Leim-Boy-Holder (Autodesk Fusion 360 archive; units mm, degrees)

design "Leim-Boy-Holder" references "Base"
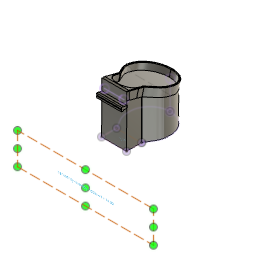
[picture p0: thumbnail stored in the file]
parameter "padding" = 5
parameter "wall_thickness" = 3
parameter "height" = 14
parameter "bottle_bottom_height" = 24
component_insert "Component Insert"
sketch "Reference" plane through (0, 55.6118, 0) normal (0, 1, 0) x axis (-1, 0, 0)
  line L1 (0, 52.4859) -> (0, 47.1259)
  line L2 (-40, 52.4859) -> (0, 52.4859)
  line L3 (-40, 47.1259) -> (-40, 52.4859)
  line L4 (0, 47.1259) -> (-40, 47.1259)
  line L5 (-40, 60) -> (0, 60)
canvas "Canvas2"
sketch "Leim Boy Base" plane through (0, 0, 0) normal (0, 0, 1) x axis (1, 0, 0)
  line L1 (-18.3701, 3.7479) -> (86.6381, 2.2286)
  curve K1 (-18.3701, 3.7479) -> (86.6381, 2.2286)
  curve K2 (86.889, 9.7087) -> (86.3872, -5.2516)
  curve K3 (83.9228, 20.464) -> (88.3484, -2.1492)
  curve K4 (57.7933, 21.4643) -> (85.6809, 20.0093)
  curve K5 (27.9092, 40.0205) -> (51.6261, 26.3959)
  curve K6 (54.8294, 23.88) -> (63.7814, 18.7373)
  curve K7 (26.0434, 38.2552) -> (33.2573, 36.115)
  curve K8 (2.0377, 36.5037) -> (24.2104, 38.799)
  curve K9 (-18.716, -11.6628) -> (-18.0242, 19.1587)
  line L2 (-18.3701, 3.7479) -> (86.6381, 2.2286)
  curve K10 (-18.3701, 3.7479) -> (86.6381, 2.2286)
  curve K11 (86.6725, -5.2557) -> (86.6037, 9.7128)
  curve K12 (83.3963, -15.9207) -> (88.4744, 6.5551)
  curve K13 (57.2488, -16.1646) -> (85.1669, -15.517)
  curve K14 (54.2163, -18.4935) -> (63.3134, -13.612)
  curve K15 (26.8403, -33.8484) -> (50.9415, -20.9157)
  curve K16 (25.0265, -32.0299) -> (32.2993, -30.0992)
  curve K17 (1.0814, -29.5846) -> (23.1785, -32.5204)
  curve K18 (-18.27, 19.1623) -> (-18.4703, -11.6664)
  curve K19 (61.6573, 25.7332) -> (91.6382, 2.1562)
  curve K20 (-23.3698, 3.8203) -> (61.6573, 25.7332)
  curve K21 (-23.3698, 3.8203) -> (60.9877, -20.5435)
  curve K22 (60.9877, -20.5435) -> (91.6382, 2.1562)
  curve K23 (62.6874, 28.6657) -> (94.6382, 2.1128)
  curve K24 (-26.3696, 3.8637) -> (62.6874, 28.6657)
  curve K25 (-26.3696, 3.8637) -> (61.9325, -23.5045)
  curve K26 (61.9325, -23.5045) -> (94.6382, 2.1128)
  point P2 (86.6381, 2.2286)
  point P4 (86.1356, 9.1574)
  point P5 (71.7371, 20.7368)
  point P7 (39.7676, 33.2082)
  point P6 (59.3054, 21.3087)
  point P8 (29.6504, 37.1851)
  point P9 (13.124, 37.6514)
  point P3 (-18.3701, 3.7479)
  point P22 (24.2104, 38.799)
  point P26 (86.6381, 2.2286)
  point P27 (-18.3701, 3.7479)
  point P28 (85.9354, -4.6828)
  point P29 (71.2079, -15.8408)
  point P30 (58.7648, -16.0527)
  point P31 (38.8909, -27.382)
  point P32 (28.6629, -31.0645)
  point P33 (12.1299, -31.0525)
  point P10 (86.3872, -5.2516)
  point P34 (86.6037, 9.7128)
  point P11 (86.889, 9.7087)
  point P35 (86.6725, -5.2557)
  point P12 (88.3484, -2.1492)
  point P36 (88.4744, 6.5551)
  point P13 (83.9228, 20.464)
  point P37 (83.3963, -15.9207)
  point P14 (85.6809, 20.0093)
  point P38 (85.1669, -15.517)
  point P15 (57.7933, 21.4643)
  point P39 (57.2488, -16.1646)
  point P16 (51.6261, 26.3959)
  point P42 (50.9415, -20.9157)
  point P17 (27.9092, 40.0205)
  point P43 (26.8403, -33.8484)
  point P18 (63.7814, 18.7373)
  point P40 (63.3134, -13.612)
  point P19 (54.8294, 23.88)
  point P41 (54.2163, -18.4935)
  point P20 (33.2573, 36.115)
  point P44 (32.2993, -30.0992)
  point P21 (26.0434, 38.2552)
  point P45 (25.0265, -32.0299)
  point P46 (23.1785, -32.5204)
  point P23 (2.0377, 36.5037)
  point P47 (1.0814, -29.5846)
  point P24 (-18.0242, 19.1587)
  point P48 (-18.4703, -11.6664)
  point P25 (-18.716, -11.6628)
  point P49 (-18.27, 19.1623)
  midpoint P2 K2
  midpoint P4 K3
  midpoint P5 K4
  midpoint P7 K5
  midpoint P6 K6
  midpoint P8 K7
  midpoint P9 K8
  midpoint P3 K9
  coincident K7 P22
  parallel K5 K6
  symmetric P2 L1 P26
  symmetric P3 L1 P27
  symmetric L1 P4 P28
  symmetric L1 P5 P29
  symmetric L1 P6 P30
  symmetric L1 P7 P31
  symmetric L1 P8 P32
  symmetric L1 P9 P33
  symmetric L1 P10 P34
  symmetric L1 P11 P35
  symmetric L1 P12 P36
  symmetric L1 P13 P37
  symmetric L1 P14 P38
  symmetric L1 P15 P39
  symmetric L1 P16 P42
  symmetric L1 P17 P43
  symmetric L1 P18 P40
  symmetric L1 P19 P41
  symmetric L1 P20 P44
  symmetric L1 P21 P45
  symmetric L1 P22 P46
  symmetric L1 P23 P47
  symmetric L1 P24 P48
  symmetric L1 P25 P49
  dimension "d3" = -5 (= "padding * -1")
  dimension "d8" = 8 (= "padding + wall_thickness")
extrude "Extrude1" new body sketch "Leim Boy Base" profile of K1 K10 K22 K20 K26 K24 against normal blind 3 (magnitude of "wall_thickness * -1")
extrude "Extrude2" add sketch "Leim Boy Base" profile of K22 K20 K26 K24 along normal blind 14 (= "height")
work_plane "WorkPlane1" AlongDistance 94.638
move "Move1"
work_plane "WorkPlane2" AlongDistance -2.992
sketch "Sketch5" plane through (0, 0, -2.9918) normal (0, 0, 1) x axis (1, 0, 0)
  curve K1 (59.6518, 28.6657) -> (-26.3706, 3.8637)
  curve K2 (-26.3706, 3.8637) -> (58.9226, -23.5045)
  curve K3 (58.9226, -23.5045) -> (90.5139, 2.1128)
  curve K4 (90.5139, 2.1128) -> (59.6518, 28.6657)
  line L1 (59.6518, 28.6657) -> (58.9226, -23.5045)
  line L2 (90.8789, 28.2292) -> (59.6518, 28.6657)
  line L3 (90.1497, -23.941) -> (90.8789, 28.2292)
  line L4 (58.9226, -23.5045) -> (90.1497, -23.941)
  point P3 (59.6518, 28.6657)
  point P7 (59.6518, 28.6657)
  point P4 (58.9226, -23.5045)
  point P6 (58.9226, -23.5045)
  perpendicular L1 L2
  parallel L1 L3
  parallel L2 L4
  coincident P3 P7
  coincident P4 P6
extrude "Extrude3" new body sketch "Sketch5" along normal blind 90
sketch "Sketch6" plane through (0, 0, 0) normal (0, 1, 0) x axis (1, 0, 0)
  line L1 (-26.372, 2.9922) -> (58.9226, -19.8624)
  line L2 (58.9226, -19.8624) -> (90.5139, -28.3273)
  line L3 (-26.372, -147.6316) -> (-26.372, 2.9922)
  line L4 (90.5139, -171.701) -> (90.5139, -28.3273)
  line L5 (90.5139, -147.6316) -> (-26.372, -147.6316)
  line L6 (142.865, -160.7459) -> (90.5139, -28.3273)
  line L7 (90.5139, -147.6316) -> (142.865, -160.7459)
  point P3 (-26.372, 2.9922)
  point P5 (-26.372, 2.9922)
  point P4 (90.5139, -28.3273)
  point P7 (90.5139, -28.3273)
  point P9 (90.5139, -147.6316)
  coincident P3 P5
  vertical L3
  coincident P4 P7
  vertical L4
  coincident L4 P9
  perpendicular L4 L5
extrude "Extrude4" cut sketch "Sketch6" distance 150
delete_face "DeleteFace1"
combine "Combine1"
extrude "Extrude5" add of existing geometry blind 60
move "Move2"
work_plane "WorkPlane3" AlongDistance 16
sketch "Sketch7" plane through (0, 55.6118, 0) normal (0, 1, 0) x axis (1, 0, 0)
  line L1 (40, -60) -> (0, -60)
extrude "Extrude14" add of existing geometry blind 1
move "Move5"
move "Move6" RotateAngle 1
extrude "Extrude6" new body of existing geometry blind 225
extrude "Extrude7" add of existing geometry to an object
extrude "Extrude8" cut of existing geometry to an object
work_plane "WorkPlane4" AlongDistance 172.496
sketch "Sketch9" plane through (0, 173.5061, 0) normal (0, 1, 0) x axis (1, 0, 0)
  line L1 (19.3504, 31.3217) -> (19.6214, -28.6776)
  line L2 (-70.2641, 0.9166) -> (19.4859, 1.3221)
  point P4 (19.4859, 1.3221)
  midpoint L1 P4
  perpendicular L1 L2
work_plane "WorkPlane5" RotateAngle 87
sketch "Sketch10" plane through (0.0409, 172.9664, 9.0647) normal (0.0002, 0.9986, 0.0523) x axis (-1, 0.0002, 0)
  line L1 (-19.3098, -40.3593) -> (-19.5801, 19.5578)
  line L2 (-40.1958, 7.9443) -> (1.306, 7.9443)
  line L3 (-49.1958, -19.7458) -> (-49.1958, -1.0557)
  line L4 (1.306, -28.7458) -> (-40.1958, -28.7458)
  line L5 (10.306, -1.0557) -> (10.306, -19.7458)
  line L6 (-49.1958, -28.7458) -> (10.306, 7.9443)
  line L7 (10.306, -28.7458) -> (-49.1958, 7.9443)
  arc A1 centre (-40.1958, -1.0557) radius 9 clockwise from (-49.1958, -1.0557) to (-40.1958, 7.9443)
  arc A2 centre (-40.1958, -19.7458) radius 9 clockwise from (-40.1958, -28.7458) to (-49.1958, -19.7458)
  arc A3 centre (1.306, -19.7458) radius 9 clockwise from (10.306, -19.7458) to (1.306, -28.7458)
  arc A4 centre (1.306, -1.0557) radius 9 clockwise from (1.306, 7.9443) to (10.306, -1.0557)
  point P8 (-19.4449, -10.4008)
  point P5 (-49.1958, 7.9443)
  point P6 (-49.1958, -28.7458)
  point P7 (10.306, -28.7458)
  point P4 (10.306, 7.9443)
  horizontal L2
  perpendicular L2 L3
  parallel L2 L4
  parallel L3 L5
  coincident L6 P8
  coincident L7 P8
  midpoint L1 P8
  coincident P5 L2
  coincident P5 L3
  tangent L2 A1
  tangent L3 A1
  coincident P6 L4
  coincident P6 L3
  tangent L4 A2
  tangent L3 A2
  equal A1 A2
  coincident P7 L4
  coincident P7 L5
  tangent L4 A3
  tangent L5 A3
  equal A1 A3
  coincident P4 L5
  coincident P4 L2
  tangent L5 A4
  tangent L2 A4
  equal A1 A4
  dimension "d36" radius A1 = 9
extrude "Extrude9" cut sketch "Sketch10" profile of L1 L2 L3 L4 L5 A1 A2 A3 A4 distance 60
fillet "Fillet2" radius 2
extrude "Extrude10" add of existing geometry to an object
extrude "Extrude11" add of existing geometry blind 3
extrude "Extrude13" add of existing geometry to an object
delete_face "DeleteFace2"
extrude "Extrude15" add of existing geometry blind 1
extrude "Extrude16" add of existing geometry blind 2
extrude "Extrude17" cut of existing geometry to an object
work_plane "WorkPlane7" AlongDistance 16.421
sketch "Sketch12" plane through (0.0591, 0.0021, 76.4377) normal (0.0008, 0, 1) x axis (-1, -0.0029, 0.0008)
  line L1 (5.9571, -60.9523) -> (-46.2186, -60.9523)
  line L2 (5.9571, -55.5528) -> (5.9571, -60.9523)
  line L3 (-46.2186, -55.5528) -> (5.9571, -55.5528)
  line L4 (-46.2186, -60.9523) -> (-46.2186, -55.5528)
  point P4 (5.9571, -55.5528)
  point P8 (5.9571, -55.5528)
  point P2 (-46.2186, -60.9523)
  point P6 (-46.2186, -60.9523)
  horizontal L1
  vertical L2
  horizontal L3
  vertical L4
  coincident P4 P8
  coincident P2 P6
extrude "Extrude18" add sketch "Sketch12" to an object
fillet "Fillet3" radius 1
fillet "Fillet4" radius 5
fillet "Fillet5" radius 2
sketch "Sketch13" plane through (-0.1411, -0.0012, -31.2271) normal (-0.0045, 0, -1) x axis (0.0084, -1, 0)
  line L1 (-173.3368, -20.9535) -> (-173.3306, -20.2183)
  curve K1 (-87.5266, -46.4797) -> (-173.3368, -20.9535)
  curve K2 (-86.5562, -46.4743) -> (-87.5266, -46.4797)
  line L2 (-55.2969, -46.3009) -> (-86.5562, -46.4743)
  line L3 (-55.5862, 5.8736) -> (-55.2969, -46.3009)
  line L4 (-86.9673, 5.6995) -> (-55.5862, 5.8736)
  curve K3 (-87.8159, 5.6948) -> (-86.9673, 5.6995)
  curve K4 (-173.3306, -20.2183) -> (-87.8159, 5.6948)
  curve K5
  curve K6
  curve K7
  curve K8
  point P5 (-86.5562, -46.4743)
  point P7 (-55.5862, 5.8736)
  coincident P5
  coincident P7
  dimension "d68" Text1-Height = 3
extrude "Extrude19" cut sketch "Sketch13" against normal blind 2
sketch "filename" plane through (0, 0, 0) normal (0, 1, 0) x axis (1, 0, 0)
  dimension "d71" = 5

design "Base"
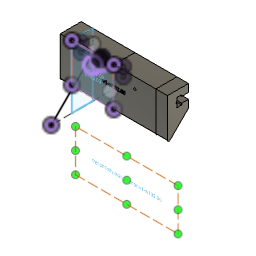
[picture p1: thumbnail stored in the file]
parameter "wall_anchor_height" = 60
parameter "wall_anchor_width" = 20
parameter "wall_anchor_angle" = 45
parameter "width_per_slot" = 40
parameter "slot_inner_width" = 8.5
parameter "slot_inner_height" = 4.5
parameter "slot_outer_width" = 5.6
parameter "slot_outer_height" = 6.5
parameter "slot_dept" = 15
parameter "print_tolerance" = 0.12
parameter "base_plate_thickness" = 16
parameter "base_plate_slot_height" = 50
parameter "wall_anchor_angle_rounded_border" = 1.5
parameter "base_plate_screw_hole_diameter" = 4
parameter "base_plate_screw_head_diameter" = 8
parameter "base_plate_screw_head_height" = 4
parameter "base_plate_screw_hole_side_distance" = 7
parameter "slot_screw_head_width" = 4.42 (= "4.3 mm + print_tolerance")
parameter "slot_screw_thread_width" = 2.12 (= "2 mm + print_tolerance")
parameter "slot_screw_head_height" = 2.12 (= "2 mm + print_tolerance")
parameter "width" = 102
parameter "filament_hole_width" = 1.7
parameter "plate_height" = 50
sketch "Side" plane through (0, 0, 0) normal (1, 0, 0) x axis (0, 1, 0)
  line L1 (39.6118, 0) -> (19.6118, 0)
  line L2 (39.6118, 60) -> (39.6118, 0)
  line L3 (19.6118, 60) -> (39.6118, 60)
  line L4 (19.6118, 0) -> (19.6118, 60)
  line L5 (39.6118, 39.6118) -> (0, 0)
  line L6 (56.0196, 0) -> (0, 0)
  point P1 (0, 0)
  point P6 (0, 0)
  point P7 (39.6118, 39.6118)
  point P2 (19.6118, 0)
  point P3 (39.6118, 0)
  point P5 (19.6118, 60)
  horizontal L1
  vertical L2
  horizontal L3
  vertical L4
  horizontal L6
  coincident P1 P6
  coincident L2 P7
  dimension "d4" distance P2 P3 = 20 (= "wall_anchor_width")
  dimension "d5" distance P2 P5 = 60 (= "wall_anchor_height")
  dimension "d6" angle L5 L6 = 45 (= "wall_anchor_angle")
extrude "Extrude1" new body sketch "Side" profile of L1 L2 L3 L4 L5 along normal blind 40 (= "width_per_slot")
sketch "Slot LeftToRight" plane through (0, 0, 0) normal (-1, 0, 0) x axis (0, -1, 0)
  line L1 (-19.6118, 60) -> (-19.6118, 19.6118)
  line L2 (-39.6118, 60) -> (-19.6118, 60)
  line L3 (-39.6118, 39.6118) -> (-39.6118, 60)
  line L4 (-19.6118, 19.6118) -> (-39.6118, 39.6118)
  line L5 (-39.6118, 52.6059) -> (-39.6118, 49.8059)
  line L6 (-39.6118, 47.0059) -> (-39.6118, 49.8059)
  line L7 (-33.1118, 52.6059) -> (-39.6118, 52.6059)
  line L8 (-28.6118, 49.8059) -> (-39.6118, 49.8059)
  line L9 (-28.6118, 54.0559) -> (-28.6118, 49.8059)
  line L10 (-33.1118, 54.0559) -> (-28.6118, 54.0559)
  line L11 (-33.1118, 52.6059) -> (-33.1118, 54.0559)
  line L12 (-28.6118, 45.5559) -> (-28.6118, 49.8059)
  line L13 (-33.1118, 45.5559) -> (-28.6118, 45.5559)
  line L14 (-33.1118, 47.0059) -> (-33.1118, 45.5559)
  line L15 (-33.1118, 47.0059) -> (-39.6118, 47.0059)
  point P6 (-39.6118, 49.8059)
  point P7 (-39.6118, 52.6059)
  point P17 (-39.6118, 47.0059)
  point P9 (-33.1118, 52.6059)
  point P16 (-33.1118, 47.0059)
  point P10 (-28.6118, 49.8059)
  point P13 (-28.6118, 49.8059)
  point P11 (-28.6118, 54.0559)
  point P14 (-28.6118, 45.5559)
  point P12 (-33.1118, 54.0559)
  point P15 (-33.1118, 45.5559)
  midpoint L3 P6
  parallel L3 L5
  parallel L3 L6
  perpendicular L3 L7
  perpendicular L6 L8
  perpendicular L8 L9
  perpendicular L9 L10
  symmetric P7 L8 P17
  symmetric P9 L8 P16
  symmetric P10 L8 P13
  symmetric L8 P11 P14
  symmetric L8 P12 P15
  dimension "d80" distance P6 P7 = 2.8 (= "slot_outer_width / 2")
  dimension "d82" distance P7 P9 = 6.5 (= "slot_outer_height")
  dimension "d84" distance P6 P10 = 11 (= "slot_outer_height + slot_inner_height")
  dimension "d85" distance P10 P11 = 4.25 (= "slot_inner_width / 2")
  dimension "d86" distance P11 P12 = 4.5 (= "slot_inner_height")
extrude "Extrude3" cut sketch "Slot LeftToRight" profile of L3 L5 L6 L7 L9 L10 L11 L12 L13 L14 L15 against normal blind 40 (magnitude of "width_per_slot * -1")
sketch "Plate" plane through (0, 39.6118, 0) normal (0, 1, 0) x axis (-1, 0, 0)
  line L1 (0, 39.6118) -> (-40, 39.6118)
  line L2 (-40, 60) -> (0, 60)
  line L3 (0, 10) -> (0, 60)
  line L4 (-40, 10) -> (-40, 60)
  line L5 (-40, 10) -> (0, 10)
  line L6 (-40, 47.0059) -> (0, 47.0059)
  line L7 (-40, 52.6059) -> (-40, 60)
  line L8 (0, 60) -> (0, 52.6059)
  line L9 (0, 52.6059) -> (-40, 52.6059)
  line L10 (-40, 60) -> (0, 60)
  line L11 (-40, 39.6118) -> (-40, 47.0059)
  line L12 (0, 47.0059) -> (0, 39.6118)
  point P2 (0, 60)
  point P3 (-40, 60)
  point P4 (0, 10)
  point P5 (-40, 10)
  perpendicular L1 L3
  perpendicular L1 L4
  dimension "d36" distance P2 P3 = 40 (= "width_per_slot")
  dimension "d37" distance P2 P4 = 50 (= "base_plate_slot_height")
  dimension "d39" distance P3 P5 = 50 (= "base_plate_slot_height")
extrude "Extrude6" new body sketch "Plate" profile of L1 L2 L3 L4 L5 L6 L7 L8 L9 L10 along normal blind 16 (= "base_plate_thickness") bodies "Base plate with slot"
sketch "Slot" plane through (0, 0, 0) normal (-1, 0, 0) x axis (0, -1, 0)
  line L1 (-19.6118, 60) -> (-19.6118, 19.6118)
  line L2 (-39.6118, 60) -> (-19.6118, 60)
  line L3 (-39.6118, 52.6059) -> (-39.6118, 60)
  line L4 (-33.1118, 52.6059) -> (-39.6118, 52.6059)
  line L5 (-33.1118, 54.0559) -> (-33.1118, 52.6059)
  line L6 (-28.6118, 54.0559) -> (-33.1118, 54.0559)
  line L7 (-28.6118, 45.5559) -> (-28.6118, 54.0559)
  line L8 (-33.1118, 45.5559) -> (-28.6118, 45.5559)
  line L9 (-33.1118, 47.0059) -> (-33.1118, 45.5559)
  line L10 (-39.6118, 47.0059) -> (-33.1118, 47.0059)
  line L11 (-39.6118, 39.6118) -> (-39.6118, 47.0059)
  line L12 (-19.6118, 19.6118) -> (-39.6118, 39.6118)
  line L13 (-33.1118, 52.6059) -> (-39.6118, 52.6059)
  line L14 (-33.1118, 54.0559) -> (-33.1118, 52.6059)
  line L15 (-28.6118, 54.0559) -> (-33.1118, 54.0559)
  line L16 (-28.6118, 45.5559) -> (-28.6118, 54.0559)
  line L17 (-33.1118, 45.5559) -> (-28.6118, 45.5559)
  line L18 (-33.1118, 47.0059) -> (-33.1118, 45.5559)
  line L19 (-39.6118, 47.0059) -> (-33.1118, 47.0059)
  line L20 (-39.6118, 10) -> (-39.6118, 60)
  line L21 (-32.9918, 52.4859) -> (-39.6118, 52.4859)
  line L22 (-32.9918, 53.9359) -> (-32.9918, 52.4859)
  line L23 (-28.7318, 53.9359) -> (-32.9918, 53.9359)
  line L24 (-28.7318, 45.6759) -> (-28.7318, 53.9359)
  line L25 (-32.9918, 45.6759) -> (-28.7318, 45.6759)
  line L26 (-32.9918, 47.1259) -> (-32.9918, 45.6759)
  line L27 (-39.6118, 47.1259) -> (-32.9918, 47.1259)
  line L28 (-33.1118, 52.6059) -> (-39.6118, 52.6059)
  line L29 (-33.1118, 52.6059) -> (-33.1118, 54.0559)
  line L30 (-28.6118, 54.0559) -> (-33.1118, 54.0559)
  line L31 (-28.6118, 45.5559) -> (-28.6118, 54.0559)
  line L32 (-33.1118, 45.5559) -> (-28.6118, 45.5559)
  line L33 (-33.1118, 47.0059) -> (-33.1118, 45.5559)
  line L34 (-39.6118, 47.0059) -> (-33.1118, 47.0059)
  line L35 (-39.6118, 47.0059) -> (-39.6118, 52.6059)
  line L36 (-49.1118, 52.6059) -> (-55.6118, 52.6059)
  line L37 (-49.1118, 52.6059) -> (-49.1118, 54.0559)
  line L38 (-44.6118, 54.0559) -> (-49.1118, 54.0559)
  line L39 (-44.6118, 45.5559) -> (-44.6118, 54.0559)
  line L40 (-49.1118, 45.5559) -> (-44.6118, 45.5559)
  line L41 (-49.1118, 47.0059) -> (-49.1118, 45.5559)
  line L42 (-55.6118, 47.0059) -> (-49.1118, 47.0059)
  line L43 (-55.6118, 47.0059) -> (-55.6118, 52.6059)
  point P15 (-39.6118, 52.6059)
  point P33 (-39.6118, 52.6059)
  point P16 (-33.1118, 52.6059)
  point P34 (-33.1118, 52.6059)
  point P17 (-33.1118, 54.0559)
  point P35 (-33.1118, 54.0559)
  point P36 (-33.1118, 52.6059)
  point P18 (-28.6118, 54.0559)
  point P37 (-28.6118, 54.0559)
  point P19 (-28.6118, 45.5559)
  point P38 (-28.6118, 45.5559)
  point P10 (-28.6118, 45.5559)
  point P39 (-28.6118, 45.5559)
  point P11 (-33.1118, 45.5559)
  point P40 (-33.1118, 45.5559)
  point P41 (-33.1118, 45.5559)
  point P12 (-33.1118, 47.0059)
  point P42 (-33.1118, 47.0059)
  point P21 (-33.1118, 47.0059)
  point P43 (-33.1118, 47.0059)
  point P22 (-39.6118, 47.0059)
  point P44 (-39.6118, 47.0059)
  point P45 (-39.6118, 52.6059)
  point P46 (-39.6118, 47.0059)
  coincident P15 P33
  coincident P16 P34
  coincident P17 P35
  coincident P16 P36
  coincident P18 P37
  coincident P19 P38
  coincident P10 P39
  coincident P11 P40
  coincident P11 P41
  coincident P12 P42
  coincident P21 P43
  coincident P22 P44
  coincident P15 P45
  coincident P22 P46
  dimension "d91" = 0.12 (= "print_tolerance")
  dimension "d96" R-Pattern1-uDistance = -16 (= "base_plate_thickness * -1")
  dimension "d97" R-Pattern1-vDistance = 0
extrude "Extrude7" add sketch "Slot" profile of L20 L24 L23 L27 L22 L25 L26 L21 against normal blind 40 (magnitude of "width_per_slot * -1")
extrude "Extrude8" cut sketch "Slot" profile of L36 L37 L38 L39 L40 L41 L42 L43 no distance stored
sketch "Sketch3" plane through (0, 0, 0) normal (-1, 0, 0) x axis (0, -1, 0)
  line L1 (-32.9918, 47.1259) -> (-39.6118, 47.1259)
  line L2 (-32.9918, 45.6759) -> (-32.9918, 47.1259)
  line L3 (-28.7318, 45.6759) -> (-32.9918, 45.6759)
  line L4 (-28.7318, 53.9359) -> (-28.7318, 45.6759)
  line L5 (-32.9918, 53.9359) -> (-28.7318, 53.9359)
  line L6 (-32.9918, 52.4859) -> (-32.9918, 53.9359)
  line L7 (-39.6118, 52.4859) -> (-32.9918, 52.4859)
  line L8 (-44.6118, 45.5559) -> (-44.6118, 54.0559)
  line L9 (-32.9918, 52.4859) -> (-39.6118, 52.4859)
  line L10 (-32.9918, 53.9359) -> (-32.9918, 52.4859)
  line L11 (-28.7318, 53.9359) -> (-32.9918, 53.9359)
  line L12 (-28.7318, 45.6759) -> (-28.7318, 53.9359)
  line L13 (-32.9918, 45.6759) -> (-28.7318, 45.6759)
  line L14 (-32.9918, 47.1259) -> (-32.9918, 45.6759)
  line L15 (-39.6118, 47.1259) -> (-32.9918, 47.1259)
  line L16 (-39.6118, 47.1259) -> (-39.6118, 52.4859)
  line L17 (-55.6118, 52.4859) -> (-48.9918, 52.4859)
  line L18 (-48.9918, 52.4859) -> (-48.9918, 53.9359)
  line L19 (-48.9918, 53.9359) -> (-44.7318, 53.9359)
  line L20 (-44.7318, 45.6759) -> (-44.7318, 53.9359)
  line L21 (-48.9918, 45.6759) -> (-44.7318, 45.6759)
  line L22 (-48.9918, 47.1259) -> (-48.9918, 45.6759)
  line L23 (-55.6118, 47.1259) -> (-48.9918, 47.1259)
  line L24 (-55.6118, 47.1259) -> (-55.6118, 52.4859)
  line L25 (-55.6118, 47.0059) -> (-49.1118, 47.0059)
  line L26 (-55.6118, 10) -> (-55.6118, 47.0059)
  line L27 (-39.6118, 10) -> (-55.6118, 10)
  line L28 (-39.6118, 47.1259) -> (-39.6118, 10)
  line L29 (-39.6118, 60) -> (-39.6118, 52.4859)
  line L30 (-55.6118, 60) -> (-39.6118, 60)
  line L31 (-55.6118, 52.6059) -> (-55.6118, 60)
  line L32 (-49.1118, 52.6059) -> (-55.6118, 52.6059)
  line L33 (-49.1118, 54.0559) -> (-49.1118, 52.6059)
  line L34 (-44.6118, 54.0559) -> (-49.1118, 54.0559)
  line L35 (-49.1118, 45.5559) -> (-44.6118, 45.5559)
  line L36 (-49.1118, 47.0059) -> (-49.1118, 45.5559)
  point P9 (-39.6118, 52.4859)
  point P20 (-39.6118, 52.4859)
  point P19 (-39.6118, 47.1259)
  point P21 (-39.6118, 47.1259)
  coincident P9 P20
  coincident P19 P21
  dimension "d105" R-Pattern1-vDistance = 0
extrude "Extrude3" new body sketch "Sketch3" profile of L17 L18 L19 L20 L21 L22 L23 L24 against normal blind 40 (magnitude of "width_per_slot * -1")
sketch "Screw hole" plane through (0, 28.6118, 0) normal (0, 1, 0) x axis (-1, 0, 0)
  line L1 (0, 54.0559) -> (0, 45.5559)
  line L2 (-40, 54.0559) -> (0, 54.0559)
  line L3 (-40, 45.5559) -> (-40, 54.0559)
  line L4 (0, 45.5559) -> (-40, 45.5559)
  line L5 (0, 45.5559) -> (-40, 54.0559)
  line L6 (-40, 45.5559) -> (0, 54.0559)
  circle C1 centre (-20, 49.8059) radius 2.21
  circle C2 centre (-20, 49.8059) radius 1.06
  point P4 (-40, 54.0559)
  point P6 (-40, 54.0559)
  point P2 (0, 45.5559)
  point P7 (0, 45.5559)
  point P3 (0, 54.0559)
  point P8 (0, 54.0559)
  point P5 (-40, 45.5559)
  point P9 (-40, 45.5559)
  point P10 (-20, 49.8059)
  coincident P4 P6
  coincident P2 P7
  coincident P3 P8
  coincident P5 P9
  midpoint L5 P10
  concentric C1 C2
  dimension "d119" diameter C1 = 4.42 (= "slot_screw_head_width")
  dimension "d120" diameter C2 = 2.12 (= "slot_screw_thread_width")
extrude "Extrude4" cut sketch "Screw hole" profile of C2 against normal blind 2000
extrude "Extrude5" cut sketch "Screw hole" profile of C1 C2 no distance stored
fillet "Fillet1" radius 1.5 (= "wall_anchor_angle_rounded_border")
work_plane "WorkPlane1" sketch "Slot LeftToRight" AlongDistance -20 (= "-width_per_slot / 2")
sketch "Screw head" plane through (20, 0, 0) normal (-1, 0, 0) x axis (0, -1, 0)
  line L1 (-28.6118, 52.0159) -> (-28.6118, 47.5959)
  line L2 (-26.4918, 52.0159) -> (-26.4918, 47.5959)
  line L3 (-26.4918, 48.7459) -> (-26.4918, 50.8659)
  line L4 (-26.4918, 50.8659) -> (-28.6118, 52.0159)
  line L5 (-26.4918, 52.0159) -> (-28.6118, 52.0159)
  point P3 (-28.6118, 52.0159)
  point P8 (-28.6118, 52.0159)
  point P6 (-26.4918, 50.8659)
  point P9 (-26.4918, 50.8659)
  point P10 (-28.6118, 52.0159)
  point P5 (-26.4918, 52.0159)
  point P11 (-26.4918, 52.0159)
  coincident P3 P8
  coincident P6 P9
  coincident P3 P10
  coincident P5 P11
revolve "Revolve1" sketch "Screw head" AlongAngle 360
sketch "Plate" plane through (0, 39.6118, 0) normal (0, 1, 0) x axis (-1, 0, 0)
  line L1 (0, 39.6118) -> (-40, 39.6118)
  line L2 (-40, 60) -> (0, 60)
  line L3 (0, 10) -> (0, 60)
  line L4 (-40, 10) -> (-40, 60)
  line L5 (-40, 10) -> (0, 10)
  line L6 (-40, 47.0059) -> (0, 47.0059)
  line L7 (-40, 39.6118) -> (-40, 47.0059)
  line L8 (0, 47.0059) -> (0, 39.6118)
  line L9 (0, 52.6059) -> (-40, 52.6059)
  line L10 (-40, 60) -> (0, 60)
  line L11 (0, 60) -> (0, 52.6059)
  line L12 (-40, 52.6059) -> (-40, 60)
  point P2 (0, 60)
  point P3 (-40, 60)
  point P4 (0, 10)
  point P5 (-40, 10)
  perpendicular L1 L3
  perpendicular L1 L4
  dimension "d36_1" distance P2 P3 = 40 (= "width_per_slot")
  dimension "d37_1" distance P2 P4 = 50 (= "base_plate_slot_height")
  dimension "d39_1" distance P3 P5 = 50 (= "base_plate_slot_height")
extrude "Extrude6" new body sketch "Plate" profile of L1 L2 L3 L4 L5 L6 L7 L8 L9 L10 along normal blind 16 (= "base_plate_thickness") named "d89_1" bodies "Base plate with slot"
sketch "Slot" plane through (0, 0, 0) normal (-1, 0, 0) x axis (0, -1, 0)
  line L1 (-19.6118, 60) -> (-19.6118, 23.2332)
  line L2 (-39.6118, 60) -> (-19.6118, 60)
  line L3 (-39.6118, 52.6059) -> (-39.6118, 60)
  line L4 (-33.1118, 52.6059) -> (-39.6118, 52.6059)
  line L5 (-33.1118, 54.0559) -> (-33.1118, 52.6059)
  line L6 (-28.6118, 54.0559) -> (-33.1118, 54.0559)
  line L7 (-28.6118, 45.5559) -> (-28.6118, 54.0559)
  line L8 (-33.1118, 45.5559) -> (-28.6118, 45.5559)
  line L9 (-33.1118, 47.0059) -> (-33.1118, 45.5559)
  line L10 (-39.6118, 47.0059) -> (-33.1118, 47.0059)
  line L11 (-39.6118, 39.6118) -> (-39.6118, 47.0059)
  line L12 (-22.1725, 22.1725) -> (-39.6118, 39.6118)
  line L13 (-33.1118, 52.6059) -> (-39.6118, 52.6059)
  line L14 (-33.1118, 54.0559) -> (-33.1118, 52.6059)
  line L15 (-28.6118, 54.0559) -> (-33.1118, 54.0559)
  line L16 (-28.6118, 45.5559) -> (-28.6118, 54.0559)
  line L17 (-33.1118, 45.5559) -> (-28.6118, 45.5559)
  line L18 (-33.1118, 47.0059) -> (-33.1118, 45.5559)
  line L19 (-39.6118, 47.0059) -> (-33.1118, 47.0059)
  line L20 (-39.6118, 10) -> (-39.6118, 60)
  line L21 (-32.9918, 52.4859) -> (-39.6118, 52.4859)
  line L22 (-32.9918, 53.9359) -> (-32.9918, 52.4859)
  line L23 (-28.7318, 53.9359) -> (-32.9918, 53.9359)
  line L24 (-28.7318, 45.6759) -> (-28.7318, 53.9359)
  line L25 (-32.9918, 45.6759) -> (-28.7318, 45.6759)
  line L26 (-32.9918, 47.1259) -> (-32.9918, 45.6759)
  line L27 (-39.6118, 47.1259) -> (-32.9918, 47.1259)
  line L28 (-33.1118, 52.6059) -> (-39.6118, 52.6059)
  line L29 (-33.1118, 52.6059) -> (-33.1118, 54.0559)
  line L30 (-28.6118, 54.0559) -> (-33.1118, 54.0559)
  line L31 (-28.6118, 45.5559) -> (-28.6118, 54.0559)
  line L32 (-33.1118, 45.5559) -> (-28.6118, 45.5559)
  line L33 (-33.1118, 47.0059) -> (-33.1118, 45.5559)
  line L34 (-39.6118, 47.0059) -> (-33.1118, 47.0059)
  line L35 (-39.6118, 47.0059) -> (-39.6118, 52.6059)
  line L36 (-49.1118, 52.6059) -> (-55.6118, 52.6059)
  line L37 (-49.1118, 52.6059) -> (-49.1118, 54.0559)
  line L38 (-44.6118, 54.0559) -> (-49.1118, 54.0559)
  line L39 (-44.6118, 45.5559) -> (-44.6118, 54.0559)
  line L40 (-49.1118, 45.5559) -> (-44.6118, 45.5559)
  line L41 (-49.1118, 47.0059) -> (-49.1118, 45.5559)
  line L42 (-55.6118, 47.0059) -> (-49.1118, 47.0059)
  line L43 (-55.6118, 47.0059) -> (-55.6118, 52.6059)
  arc A1 centre (-21.1118, 23.2332) radius 1.5 clockwise from (-19.6118, 23.2332) to (-22.1725, 22.1725)
  point P15 (-39.6118, 52.6059)
  point P33 (-39.6118, 52.6059)
  point P16 (-33.1118, 52.6059)
  point P34 (-33.1118, 52.6059)
  point P17 (-33.1118, 54.0559)
  point P35 (-33.1118, 54.0559)
  point P36 (-33.1118, 52.6059)
  point P18 (-28.6118, 54.0559)
  point P37 (-28.6118, 54.0559)
  point P19 (-28.6118, 45.5559)
  point P38 (-28.6118, 45.5559)
  point P10 (-28.6118, 45.5559)
  point P39 (-28.6118, 45.5559)
  point P11 (-33.1118, 45.5559)
  point P40 (-33.1118, 45.5559)
  point P41 (-33.1118, 45.5559)
  point P12 (-33.1118, 47.0059)
  point P42 (-33.1118, 47.0059)
  point P21 (-33.1118, 47.0059)
  point P43 (-33.1118, 47.0059)
  point P22 (-39.6118, 47.0059)
  point P44 (-39.6118, 47.0059)
  point P45 (-39.6118, 52.6059)
  point P46 (-39.6118, 47.0059)
  coincident P15 P33
  coincident P16 P34
  coincident P17 P35
  coincident P16 P36
  coincident P18 P37
  coincident P19 P38
  coincident P10 P39
  coincident P11 P40
  coincident P11 P41
  coincident P12 P42
  coincident P21 P43
  coincident P22 P44
  coincident P15 P45
  coincident P22 P46
  dimension "d91_1" = 0.12 (= "print_tolerance")
  dimension "d96_1" R-Pattern1-uDistance = -16 (= "base_plate_thickness * -1")
  dimension "d97_1" R-Pattern1-vDistance = 0
extrude "Extrude8" cut sketch "Slot" profile of L36 L37 L38 L39 L40 L41 L42 L43 no distance stored
sketch "Screw" plane through (0, 55.6118, 0) normal (0, 1, 0) x axis (-1, 0, 0)
  line L1 (-40, 47.0059) -> (0, 47.0059)
  line L2 (-40, 10) -> (-40, 47.0059)
  line L3 (0, 10) -> (-40, 10)
  line L4 (0, 47.0059) -> (0, 10)
  line L5 (-33, 17) -> (-33, 40.0059)
  line L6 (-7, 17) -> (-33, 17)
  line L7 (-7, 40.0059) -> (-7, 17)
  line L8 (-33, 40.0059) -> (-7, 40.0059)
  circle C1 centre (-33, 17) radius 4
  circle C2 centre (-33, 17) radius 2
  point P7 (-33, 17)
  point P10 (-33, 17)
  coincident P7 P10
  concentric C1 C2
  dimension "d127" = -7 (= "base_plate_screw_hole_side_distance * -1")
  dimension "d128" diameter C1 = 8
  dimension "d129" diameter C2 = 4
rectangular_pattern "R-Pattern2" countU 2 (= "floor(( width / mm ) / ( width_per_slot / cm * 10 ))") uSpaceDistance 40 (= "width_per_slot") vSpaceDistance 0 bodies "Wall anchor part (1)"
work_plane "WorkPlane2"
extrude "Extrude12" new body of existing geometry no distance stored
mirror "Mirror3" mirrorStitchTolerance 0.1
sketch "filename" plane through (0, 19.6118, 0) normal (0, -1, 0) x axis (1, 0, 0)
  dimension "d216" = 3
sketch "Text" plane through (0, 19.6118, 0) normal (0, -1, 0) x axis (1, 0, 0)
  line L1 (91, 60) -> (91, 23.2332)
  line L2 (80, 23.2332) -> (80, 60)
  line L3 (91, 23.2332) -> (80, 23.2332)
  line L4 (91, 60) -> (91, 23.2332)
  line L5 (80, 60) -> (91, 60)
  line L6 (0, 60) -> (0, 23.2332)
  line L7 (-11, 60) -> (0, 60)
  line L8 (-11, 23.2332) -> (-11, 60)
  line L9 (0, 23.2332) -> (-11, 23.2332)
  curve K1
  curve K2
  curve K3
  curve K4
  line L10 (80, 60) -> (40, 60)
  point P4 (91, 23.2332)
  point P2 (-11, 60)
  coincident P4
  coincident P2
  parallel K3 L10
  dimension "d229" Text1-Height = 3
extrude "Extrude19" cut sketch "Text" against normal blind 2
extrude "Extrude14" cut of existing geometry blind 31 (= "( width_per_slot - width ) / -2")
extrude "Extrude15" cut of existing geometry blind 31 (= "( width_per_slot - width ) / -2")
extrude "Extrude9" cut of existing geometry blind -39 (= "-width_per_slot + 1 mm")
extrude "Extrude10" add of existing geometry blind 101 (= "width - 1 mm")
extrude "Extrude13" cut of existing geometry blind -30
extrude "Extrude14" add of existing geometry blind 50 (= "plate_height")
sketch "Sketch7" plane through (0, 39.6118, 0) normal (0, -1, 0) x axis (1, 0, 0)
  dimension "d236" = 3
extrude "Extrude11" cut sketch "Sketch7" against normal blind 2
sketch "File name" plane through (0, 39.6118, 0) normal (0, -1, 0) x axis (1, 0, 0)
  line L1 (43.897, 22.4163) -> (43.6596, 22.4163)
  line L2 (43.897, 19.404) -> (43.897, 22.4163)
  line L3 (43.5286, 19.404) -> (43.897, 19.404)
  line L4 (43.5286, 21.7512) -> (43.5286, 19.404)
  curve K1 (43.1787, 21.4975) -> (43.5286, 21.7512)
  curve K2 (42.7919, 21.3072) -> (43.1787, 21.4975)
  line L5 (42.7919, 21.6632) -> (42.7919, 21.3072)
  curve K3 (43.3322, 22.0152) -> (42.7919, 21.6632)
  curve K4 (43.6596, 22.4163) -> (43.3322, 22.0152)
  line L6 (47.1241, 19.404) -> (47.5641, 21.0759)
  line L7 (46.7394, 19.404) -> (47.1241, 19.404)
  line L8 (46.0744, 21.5773) -> (46.7394, 19.404)
  line L9 (46.455, 21.5773) -> (46.0744, 21.5773)
  line L10 (46.8008, 20.3228) -> (46.455, 21.5773)
  line L11 (46.9297, 19.8563) -> (46.8008, 20.3228)
  curve K5 (47.0423, 20.3044) -> (46.9297, 19.8563)
  line L12 (47.3881, 21.5773) -> (47.0423, 20.3044)
  line L13 (47.7667, 21.5773) -> (47.3881, 21.5773)
  line L14 (48.0921, 20.3167) -> (47.7667, 21.5773)
  line L15 (48.2005, 19.9013) -> (48.0921, 20.3167)
  line L16 (48.3254, 20.3208) -> (48.2005, 19.9013)
  line L17 (48.6978, 21.5773) -> (48.3254, 20.3208)
  line L18 (49.0559, 21.5773) -> (48.6978, 21.5773)
  line L19 (48.3765, 19.404) -> (49.0559, 21.5773)
  line L20 (47.9939, 19.404) -> (48.3765, 19.404)
  line L21 (47.648, 20.7055) -> (47.9939, 19.404)
  line L22 (47.5641, 21.0759) -> (47.648, 20.7055)
  line L23 (45.9311, 20.3044) -> (45.9311, 20.6748)
  line L24 (44.7995, 20.3044) -> (45.9311, 20.3044)
  line L25 (44.7995, 20.6748) -> (44.7995, 20.3044)
  line L26 (45.9311, 20.6748) -> (44.7995, 20.6748)
  line L27 (41.4638, 19.404) -> (42.2865, 21.5773)
  line L28 (41.1201, 19.404) -> (41.4638, 19.404)
  line L29 (40.2933, 21.5773) -> (41.1201, 19.404)
  line L30 (40.6821, 21.5773) -> (40.2933, 21.5773)
  line L31 (41.1487, 20.2758) -> (40.6821, 21.5773)
  curve K6 (41.2879, 19.8379) -> (41.1487, 20.2758)
  curve K7 (41.425, 20.2512) -> (41.2879, 19.8379)
  line L32 (41.9079, 21.5773) -> (41.425, 20.2512)
  line L33 (42.2865, 21.5773) -> (41.9079, 21.5773)
  line L34 (0, 47.1259) -> (102, 47.1259)
  line L35 (0, -10) -> (0, 47.1259)
  line L36 (102, 47.1259) -> (102, -10)
  curve K8
  curve K9
  curve K10
  curve K11
  curve K12 (49.545, 21.3072) -> (49.9318, 21.4975)
  curve K13 (50.0853, 22.0152) -> (49.545, 21.6632)
  curve K14 (49.9318, 21.4975) -> (50.2817, 21.7512)
  curve K15 (50.4127, 22.4163) -> (50.0853, 22.0152)
  curve K16 (53.5498, 20.8836) -> (53.4823, 21.5916)
  line L37 (102, -10) -> (0, -10)
  line L38 (50.2817, 19.404) -> (50.6501, 19.404)
  curve K17 (54.1606, 16.2014) -> (54.4574, 14.9818)
  curve K18 (57.4195, 20.8836) -> (57.7162, 19.6639)
  curve K19 (53.4413, 20.0302) -> (53.5498, 20.8836)
  curve K20 (52.5716, 19.3529) -> (53.116, 19.5288)
  curve K21 (47.7984, 16.5861) -> (47.5447, 16.8481)
  curve K22 (49.2923, 16.3856) -> (49.7548, 16.2035)
  curve K23 (48.971, 16.3037) -> (49.2923, 16.3856)
  curve K24 (48.7459, 16.095) -> (48.971, 16.3037)
  curve K25 (50.3237, 15.7389) -> (50.0535, 16.4388)
  curve K26 (50.0863, 15.035) -> (50.3237, 15.7389)
  line L39 (55.8602, 19.404) -> (55.8602, 19.758)
  line L40 (53.8772, 19.404) -> (55.8602, 19.404)
  line L41 (46.1061, 17.7219) -> (46.1061, 14.7219)
  curve K27 (47.1252, 16.9443) -> (46.4744, 16.6455)
  curve K28 (47.5447, 16.8481) -> (47.1252, 16.9443)
  curve K29 (49.3905, 16.711) -> (48.8237, 16.5227)
  curve K30 (50.0535, 16.4388) -> (49.3905, 16.711)
  curve K31 (47.3871, 16.5002) -> (47.5078, 16.0991)
  curve K32 (53.116, 19.5288) -> (53.4413, 20.0302)
  curve K33 (51.5934, 20.8836) -> (51.8902, 19.6639)
  curve K34 (51.8902, 19.6639) -> (52.5716, 19.3529)
  curve K35 (56.0495, 16.9095) -> (55.8632, 17.3556)
  curve K36 (56.117, 16.2014) -> (56.0495, 16.9095)
  curve K37 (56.0085, 15.3481) -> (56.117, 16.2014)
  curve K38 (55.6832, 14.8467) -> (56.0085, 15.3481)
  curve K39 (55.1388, 14.6707) -> (55.6832, 14.8467)
  curve K40 (54.4574, 14.9818) -> (55.1388, 14.6707)
  curve K41 (61.2728, 19.5288) -> (61.5982, 20.0302)
  curve K42 (60.7285, 19.3529) -> (61.2728, 19.5288)
  curve K43 (60.0471, 19.6639) -> (60.7285, 19.3529)
  curve K44 (59.7503, 20.8836) -> (60.0471, 19.6639)
  curve K45 (49.7548, 16.2035) -> (49.9328, 15.7062)
  line L42 (46.4744, 16.6455) -> (46.4744, 17.7219)
  curve K46 (47.8762, 16.0991) -> (47.7984, 16.5861)
  line L43 (46.4744, 14.7219) -> (46.4744, 15.9108)
  line L44 (46.1061, 14.7219) -> (46.4744, 14.7219)
  curve K47 (48.9198, 15.1148) -> (48.7214, 15.5404)
  curve K48 (49.2984, 14.9736) -> (48.9198, 15.1148)
  curve K49 (49.7486, 15.1741) -> (49.2984, 14.9736)
  curve K50 (49.9328, 15.7062) -> (49.7486, 15.1741)
  curve K51 (51.6436, 14.6707) -> (52.1879, 14.8467)
  curve K52 (50.9621, 14.9818) -> (51.6436, 14.6707)
  curve K53 (50.6654, 16.2014) -> (50.9621, 14.9818)
  line L45 (46.4744, 17.7219) -> (46.1061, 17.7219)
  curve K54 (44.383, 14.7505) -> (44.7145, 14.6728)
  curve K55 (44.1436, 14.947) -> (44.383, 14.7505)
  curve K56 (59.3083, 21.5916) -> (59.1221, 22.0377)
  curve K57 (59.3758, 20.8836) -> (59.3083, 21.5916)
  curve K58 (59.2674, 20.0302) -> (59.3758, 20.8836)
  curve K59 (58.942, 19.5288) -> (59.2674, 20.0302)
  curve K60 (58.3977, 19.3529) -> (58.942, 19.5288)
  curve K61 (57.7162, 19.6639) -> (58.3977, 19.3529)
  curve K62 (54.2394, 22.1932) -> (53.9468, 21.5486)
  curve K63 (54.9209, 22.4163) -> (54.2394, 22.1932)
  line L46 (50.2817, 21.7512) -> (50.2817, 19.404)
  curve K64 (51.7019, 21.7389) -> (51.5934, 20.8836)
  curve K65 (52.0273, 22.2403) -> (51.7019, 21.7389)
  curve K66 (52.9952, 22.3181) -> (52.5716, 22.4163)
  curve K67 (53.296, 22.0377) -> (52.9952, 22.3181)
  curve K68 (53.4823, 21.5916) -> (53.296, 22.0377)
  curve K69 (53.9202, 19.6598) -> (53.8772, 19.404)
  curve K70 (54.1617, 20.0589) -> (53.9202, 19.6598)
  curve K71 (54.6446, 20.5132) -> (54.1617, 20.0589)
  curve K72 (55.3056, 21.1475) -> (54.6446, 20.5132)
  curve K73 (55.4775, 21.5916) -> (55.3056, 21.1475)
  curve K74 (55.3199, 21.96) -> (55.4775, 21.5916)
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  dimension "d239" Text1-Height = 3
sketch "Sketch4" plane through (40, 0, 0) normal (1, 0, 0) x axis (0, 1, 0)
  line L1 (44.7318, 53.9359) -> (48.9918, 53.9359)
  line L2 (44.7318, 45.6759) -> (44.7318, 53.9359)
  line L3 (48.9918, 45.6759) -> (44.7318, 45.6759)
  line L4 (48.9918, 47.1259) -> (48.9918, 45.6759)
  line L5 (55.6118, 47.1259) -> (48.9918, 47.1259)
  line L6 (55.6118, 52.4859) -> (55.6118, 47.1259)
  line L7 (48.9918, 52.4859) -> (55.6118, 52.4859)
  line L8 (48.9918, 53.9359) -> (48.9918, 52.4859)
  circle C1 centre (44.7318, 49.8059) radius 0.85
  point P10 (44.7318, 49.8059)
  midpoint L2 P10
  dimension "d241" diameter C1 = 1.7 (= "filament_hole_width")
extrude "Extrude4" cut sketch "Sketch4" profile of L2 C1 no distance stored
sketch "Sketch15" plane through (-11, 0, 0) normal (-1, 0, 0) x axis (0, -1, 0)
  line L1 (-19.6118, 60) -> (-19.6118, 23.2332)
  line L2 (-39.6118, 60) -> (-19.6118, 60)
  line L3 (-39.6118, 52.6059) -> (-39.6118, 60)
  line L4 (-33.1118, 52.6059) -> (-39.6118, 52.6059)
  line L5 (-33.1118, 54.0559) -> (-33.1118, 52.6059)
  line L6 (-28.6118, 54.0559) -> (-33.1118, 54.0559)
  line L7 (-28.6118, 45.5559) -> (-28.6118, 54.0559)
  line L8 (-33.1118, 45.5559) -> (-28.6118, 45.5559)
  line L9 (-33.1118, 47.0059) -> (-33.1118, 45.5559)
  line L10 (-39.6118, 47.0059) -> (-33.1118, 47.0059)
  line L11 (-39.6118, 39.6118) -> (-39.6118, 47.0059)
  line L12 (-22.1725, 22.1725) -> (-39.6118, 39.6118)
  arc A1 centre (-21.1118, 23.2332) radius 1.5 clockwise from (-19.6118, 23.2332) to (-22.1725, 22.1725)
  circle C1 centre (-28.6118, 49.8059) radius 0.85
  point P16 (-28.6118, 49.8059)
  midpoint L7 P16
  dimension "d244" diameter C1 = 1.7 (= "filament_hole_width")
sketch "Sketch9" plane through (102, 0, 0) normal (1, 0, 0) x axis (0, 1, 0)
  line L1 (49.1118, 47.0059) -> (55.6118, 47.0059)
  line L2 (49.1118, 45.5559) -> (49.1118, 47.0059)
  line L3 (44.6118, 45.5559) -> (49.1118, 45.5559)
  line L4 (44.6118, 54.0559) -> (44.6118, 45.5559)
  line L5 (49.1118, 54.0559) -> (44.6118, 54.0559)
  line L6 (49.1118, 52.6059) -> (49.1118, 54.0559)
  line L7 (55.6118, 52.6059) -> (49.1118, 52.6059)
  line L8 (55.6118, 47.0059) -> (55.6118, -10)
  line L9 (39.6118, 60) -> (55.6118, 60)
  line L10 (39.6118, 52.4859) -> (39.6118, 60)
  line L11 (32.9918, 52.4859) -> (39.6118, 52.4859)
  line L12 (32.9918, 53.9359) -> (32.9918, 52.4859)
  line L13 (28.7318, 53.9359) -> (32.9918, 53.9359)
  line L14 (28.7318, 45.6759) -> (28.7318, 53.9359)
  line L15 (32.9918, 45.6759) -> (28.7318, 45.6759)
  line L16 (32.9918, 47.1259) -> (32.9918, 45.6759)
  line L17 (39.6118, 47.1259) -> (32.9918, 47.1259)
  line L18 (55.6118, 60) -> (55.6118, 52.6059)
  line L19 (39.6118, -10) -> (39.6118, 47.1259)
  line L20 (55.6118, -10) -> (39.6118, -10)
  circle C1 centre (28.7318, 49.8059) radius 0.85
  circle C2 centre (44.6118, 49.8059) radius 0.85
  point P20 (28.7318, 49.8059)
  point P21 (44.6118, 49.8059)
  midpoint L14 P20
  midpoint L4 P21
  dimension "d247" diameter C1 = 1.7 (= "filament_hole_width")
  dimension "d250" diameter C2 = 1.7 (= "filament_hole_width")
extrude "Extrude12" cut sketch "Sketch9" profile of L4 L14 C1 C2 no distance stored
sketch "Sketch16" plane through (0, 19.6118, 0) normal (0, -1, 0) x axis (1, 0, 0)
  dimension "d253" = 3
extrude "Extrude22" cut sketch "Sketch16" against normal blind 2
extrude "Extrude23" cut sketch "Sketch15" profile of L7 C1 against normal blind 260 and along normal blind 80
sketch "Sketch17" plane through (0, 19.6118, 0) normal (0, -1, 0) x axis (1, 0, 0)
  dimension "d258" = 3
extrude "Extrude24" cut sketch "Sketch17" against normal blind 2
extrude "Extrude26" cut sketch "Text" against normal blind 2
extrude "Extrude27" cut sketch "Text" against normal blind 2
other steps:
create_component "CreateComponent1"
create_component "CreateComponent2"
create_component "CreateComponent3"
create_component "CreateComponent4"
named bodies: "Wall anchor part", "Base plate with slot", "Wall anchor part (1)"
